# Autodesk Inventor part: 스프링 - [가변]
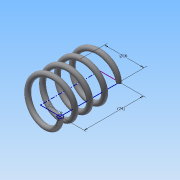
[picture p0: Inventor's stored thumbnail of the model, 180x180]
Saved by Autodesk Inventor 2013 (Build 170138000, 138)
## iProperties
Created: 2015-04
Part Number: 스프링 - [가변]
Material: 강철, 탄소
Document SubType Name: Modeling
Designer: Administrator
Density: 7.87 g/cm^3
Mass: 4.8414 g
Surface Area: 12.5818 cm^2
Volume: 0.615171 cm^3
Author: Administrator
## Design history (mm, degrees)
sketch "스케치1"
  geometry: L1 (0, 0)-(8, 0); L2 (8, 0)-(8, 20.5); L3 (8, 20.5)-(0, 20.5); L4 (0, 20.5)-(0, 0); C1 r 1 at (8, 0)
  constraints: 8 end point, 2 parallel, 1 centre point, 1 coincident, 1 horizontal, 1 perpendicular
  dimensions: "d0" = 16 diameter of L2 L4; "d2" = 20.49951 distance of L1.end L2.end (derived); "d3" = 2 diameter of C1
feature "코일1" pitch "d4" = 10; turns "d6" = 4; dims "d5" = 20.49951 (= d2), "d7" = 0, angle "d8" = 90 deg, angle "d9" = 90 deg, "d10" = 0, "d11" = 0
node "작업 평면1"
sketch "스케치2"
  geometry: L1 (-9, 0)-(-7, 0) reference; 1 further point
  constraints: 1 horizontal alignment
extrude "돌출1" cut sketch "스케치2" stored distance "d13" = 10; taper "d14" = 0 deg
node "작업 평면2"
sketch "스케치3"
  geometry: L1 (-7, 0)-(-9, 0) reference; 1 further point
  constraints: 1 horizontal alignment
extrude "돌출2" cut sketch "스케치3" stored distance "d16" = 10; taper "d17" = 0 deg
node "솔리드1"
node "절단 모서리 투영1"
node "절단 모서리 투영2"
other parameters: "d12" = 0, "d15" = 20.49951 (= d2)
